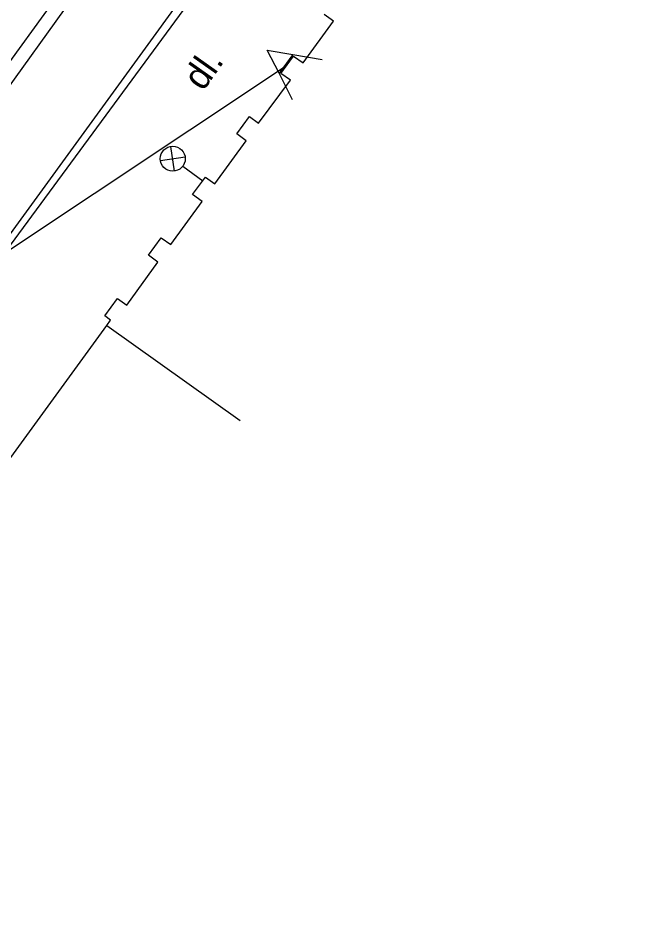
# Model space of a CAD drawing. Extents: x -599098 to -598820, y -1159597 to -1158744.
# Drawn here: x -598925.74 to -598907.27, y -1159431.56 to -1159404.15 of the extents above; entities that cross this region are included whole.
import ezdxf

# ---------------------------------------------------------------- set-up
doc = ezdxf.new("R2010")
doc.units = 0
for name, color, linetype in [('budovy', 7, 'Continuous'), ('kresba', 7, 'Continuous'), ('popisy', 7, 'Continuous'), ('trol_detaily', 7, 'Continuous'), ('trol_převěsy', 7, 'Continuous'), ('trol_troljová stopa', 7, 'Continuous'), ('trol_ved sloupy konzoly', 7, 'Continuous'), ('značky IS', 7, 'Continuous')]:
    doc.layers.add(name, color=color, linetype=linetype)

msp = doc.modelspace()

# ---------------------------------------------------------------- linework, layer by layer
at = {"layer": 'budovy'}
for p, q in [((-598916.28, -1159404.23), (-598916.56, -1159404.03)), ((-598917.19, -1159405.49), (-598916.28, -1159404.23)), ((-598917.86, -1159405.81), (-598917.48, -1159405.28)), ((-598917.48, -1159405.28), (-598917.19, -1159405.49)), ((-598918.53, -1159407.3), (-598917.57, -1159406.01)), ((-598917.57, -1159406.01), (-598917.86, -1159405.81)), ((-598919.18, -1159407.62), (-598918.8, -1159407.1)), ((-598918.8, -1159407.1), (-598918.53, -1159407.3)), ((-598918.9, -1159407.83), (-598919.18, -1159407.62)), ((-598919.84, -1159409.12), (-598918.9, -1159407.83)), ((-598920.51, -1159409.44), (-598920.12, -1159408.92)), ((-598920.12, -1159408.92), (-598919.84, -1159409.12)), ((-598920.22, -1159409.65), (-598920.51, -1159409.44)), ((-598921.16, -1159410.94), (-598920.22, -1159409.65)), ((-598921.83, -1159411.26), (-598921.45, -1159410.74)), ((-598921.45, -1159410.74), (-598921.16, -1159410.94)), ((-598921.55, -1159411.47), (-598921.83, -1159411.26)), ((-598922.49, -1159412.76), (-598921.55, -1159411.47)), ((-598923.15, -1159413.08), (-598922.77, -1159412.56)), ((-598922.77, -1159412.56), (-598922.49, -1159412.76)), ((-598922.98, -1159413.21), (-598923.15, -1159413.08)), ((-598932.23, -1159425.94), (-598923.09, -1159413.37)), ((-598923.09, -1159413.37), (-598922.98, -1159413.21)), ((-598923.09, -1159413.37), (-598919.085, -1159416.221))]:
    msp.add_line(p, q, dxfattribs=at)
at = {"layer": 'kresba'}
msp.add_line((-598954.76, -1159445), (-598910.397, -1159384.001), dxfattribs=at)
msp.add_lwpolyline([(-598971.318, -1159473.04), (-598937.35, -1159426.23), (-598935.58, -1159423.81), (-598907.272, -1159384.872)], dxfattribs=at)
at = {"layer": 'trol_detaily'}
msp.add_line((-598926.74, -1159411.99), (-598916.72, -1159398.35), dxfattribs=at)
at = {"layer": 'trol_převěsy'}
msp.add_line((-598926.84, -1159411.65), (-598917.69, -1159405.57), dxfattribs=at)
at = {"layer": 'trol_troljová stopa'}
msp.add_line((-598928.85, -1159410.14), (-598919.33, -1159396.88), dxfattribs=at)
at = {"layer": 'trol_ved sloupy konzoly'}
for p, q in [((-598917.503, -1159405.233), (-598916.622, -1159405.384)), ((-598917.509, -1159406.593), (-598917.917, -1159405.798))]:
    msp.add_line(p, q, dxfattribs=at)
msp.add_lwpolyline([(-598917.917, -1159405.798), (-598918.275, -1159405.101), (-598917.503, -1159405.233)], close=True, dxfattribs=at)
at = {"layer": 'značky IS'}
for p, q in [((-598921.05, -1159408.734), (-598921.162, -1159407.993)), ((-598921.477, -1159408.42), (-598920.736, -1159408.307)), ((-598920.804, -1159408.586), (-598920.2, -1159409.03))]:
    msp.add_line(p, q, dxfattribs=at)
msp.add_circle((-598921.106, -1159408.364), 0.375, dxfattribs=at)

# ---------------------------------------------------------------- texts
at = {"layer": 'popisy'}
msp.add_text('dl.', height=0.8, rotation=54.7618, dxfattribs=at).set_placement((-598920.198, -1159406.36))

doc.saveas('drawing.dxf')
